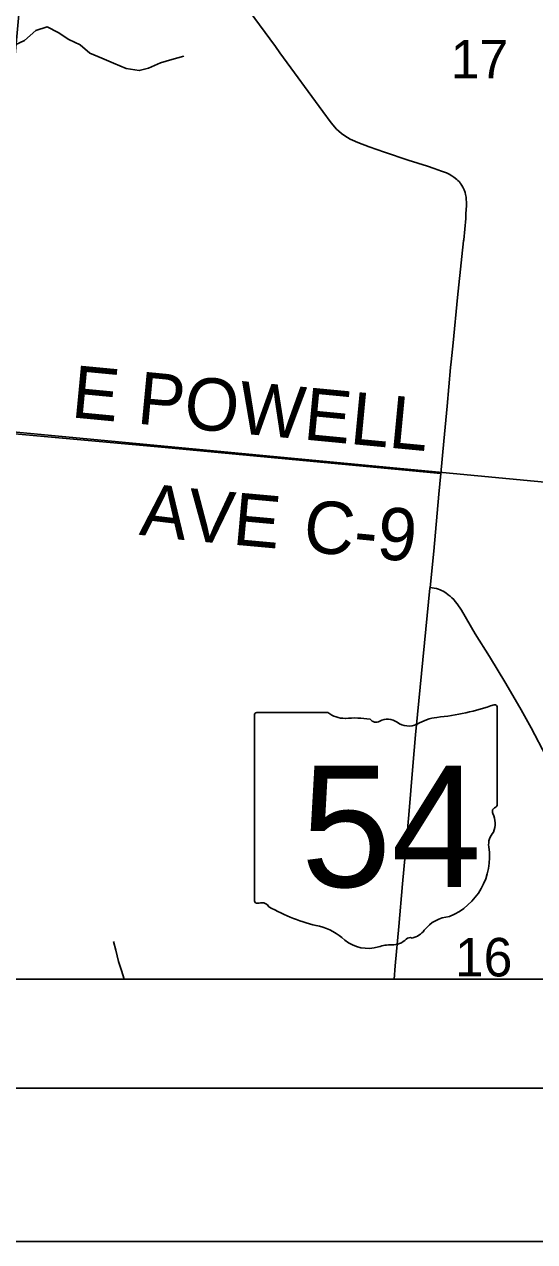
# Model space of a CAD drawing. Extents: x 0 to 1067, y 0 to 440.
# Drawn here: x 407.4 to 440.7, y 0 to 79.3 of the extents above; entities that cross this region are included whole.
import ezdxf

# ---------------------------------------------------------------- set-up
doc = ezdxf.new("R2010")
doc.units = 0
for name, color, linetype in [('GM_X_County_Road', 7, 'Continuous'), ('GM_X_County_Road_Text', 7, 'Continuous'), ('GM_X_Minor_River', 7, 'Continuous'), ('GM_X_Section', 7, 'Continuous'), ('GM_X_Section_Text', 7, 'Continuous'), ('GM_X_State_Location', 7, 'Continuous'), ('GM_X_State_Route', 7, 'Continuous'), ('GM_X_State_Shield', 7, 'Continuous'), ('GM_X_Township_Road', 7, 'Continuous'), ('SH_Border', 7, 'Continuous'), ('SH_Cut_Line', 7, 'Continuous'), ('SH_Text', 7, 'Continuous')]:
    doc.layers.add(name, color=color, linetype=linetype)

msp = doc.modelspace()

# ---------------------------------------------------------------- linework, layer by layer
at = {"layer": 'GM_X_County_Road'}
for points in [[(434.558, 50.033), (416.36, 51.756), (404.864, 52.807)], [(433.852, 42.626), (434.091, 44.99), (434.436, 48.691), (434.558, 50.033)], [(441.42, 31.603), (440.434, 33.484), (439.785, 34.657), (438.785, 36.36), (437.721, 38.112), (436.802, 39.605), (435.894, 41.147), (435.626, 41.545), (435.495, 41.711), (435.393, 41.828), (435.281, 41.944), (435.156, 42.054), (435.04, 42.146), (434.876, 42.267), (434.712, 42.368), (434.607, 42.423), (434.508, 42.47), (434.396, 42.513), (434.283, 42.545), (434.113, 42.581), (433.852, 42.626)]]:
    msp.add_lwpolyline(points, dxfattribs=at)
at = {"layer": 'GM_X_Minor_River'}
for points in [[(406.778, 77.948), (407.439, 78.262), (408.17, 78.893), (408.899, 79.137), (409.622, 78.768), (410.322, 78.307), (411.068, 77.96), (411.699, 77.432), (412.468, 77.107), (413.238, 76.783), (414.052, 76.435), (414.913, 76.292), (415.505, 76.446), (416.302, 76.804), (417.03, 77.003), (417.804, 77.224)], [(413.922, 17.107), (413.748, 17.67), (413.548, 18.241), (413.373, 18.993), (413.241, 19.563)]]:
    msp.add_lwpolyline(points, dxfattribs=at)
at = {"layer": 'GM_X_Section'}
msp.add_lwpolyline([(410.18, 114.397), (470.491, 107.701), (464.499, 47.289), (404.583, 52.958)], close=True, dxfattribs=at)
at = {"layer": 'GM_X_State_Route'}
msp.add_line((433.846, 42.567), (433.852, 42.626), dxfattribs=at)
for points in [[(435.793, 68.999), (435.762, 69.039), (435.663, 69.138), (435.599, 69.197), (435.405, 69.356), (435.277, 69.445), (435.103, 69.543), (434.92, 69.621), (434.606, 69.747), (434.13, 69.914), (433.696, 70.066), (432.431, 70.463), (430.878, 70.981), (429.88, 71.331), (429.156, 71.611), (428.803, 71.76), (428.646, 71.833), (428.474, 71.93), (428.296, 72.047), (428.087, 72.188), (427.909, 72.335), (427.768, 72.476), (427.412, 72.894), (426.863, 73.626), (424.068, 77.453), (423.792, 77.851), (421.397, 81.115)], [(436.047, 65.268), (436.176, 66.645), (436.195, 66.989), (436.22, 67.491), (436.22, 67.73), (436.215, 67.889), (436.197, 68.055), (436.17, 68.212), (436.135, 68.347), (436.071, 68.526), (435.988, 68.694), (435.924, 68.806), (435.852, 68.923), (435.824, 68.959), (435.793, 68.999)], [(435.227, 57.311), (435.361, 58.553), (435.647, 61.519), (435.917, 64.188), (436.042, 65.208), (436.047, 65.268)], [(434.558, 50.033), (434.753, 52.157), (434.964, 54.423), (435.193, 56.949), (435.227, 57.311)], [(433.852, 42.626), (434.091, 44.99), (434.436, 48.691), (434.558, 50.033)], [(431.52, 17.107), (431.591, 17.971), (431.813, 20.534), (432.051, 23.32), (432.317, 26.104), (432.466, 27.813), (432.731, 30.971), (432.916, 33.013), (433.036, 34.349), (433.846, 42.567)]]:
    msp.add_lwpolyline(points, dxfattribs=at)
at = {"layer": 'GM_X_State_Shield'}
for p, q in [((422.408, 34.269), (422.408, 22.261)), ((427.197, 34.475), (422.564, 34.475)), ((438.228, 28.492), (438.228, 34.773)), ((438.227, 28.493), (438.228, 28.492))]:
    msp.add_line(p, q, dxfattribs=at)
for centre, radius, start, end in [((432.593, 50.845), 16.777, 275.84447, 288.90645), ((438.053, 34.799), 0.176, 351.86209, 97.738), ((422.59, 34.294), 0.183, 98.1301, 188.1301), ((428.3, 35.869), 1.778, 231.61951, 271.11188), ((428.89, 27.734), 6.382, 80.48669, 94.98827), ((434.733, 30.808), 3.375, 97.34618, 120.76885), ((430.339, 34.356), 0.513, 219.79206, 297.10237), ((431.091, 32.969), 1.066, 54.46668, 119.14113), ((432.468, 34.872), 1.283, 233.85621, 294.82819), ((438.188, 28.03), 0.273, 107.94398, 210.33697), ((436.454, 27.237), 1.636, 340.03296, 23.64957), ((438.04, 28.467), 0.188, 289.60381, 7.73413), ((438.859, 25.863), 1.19, 136.8065, 186.92959), ((433.533, 25.064), 4.196, 292.30889, 8.98584), ((422.591, 22.235), 0.185, 171.95839, 258.30661), ((422.619, 23.464), 1.411, 267.33899, 280.60386), ((422.908, 21.569), 0.509, 29.74838, 93.27175), ((429.332, 32.357), 12.115, 240.41292, 257.1985), ((435.302, 18.89), 2.298, 94.40312, 142.57675), ((425.72, 16.867), 3.791, 47.18416, 75.83597), ((432.39, 21.098), 1.356, 282.87319, 323.27711), ((429.819, 21.509), 2.405, 230.70037, 286.29184), ((431.209, 17.358), 1.976, 85.69512, 111.20995), ((431.385, 20.61), 1.282, 268.77702, 315.54927), ((432.544, 19.447), 0.361, 65.75173, 132.64842)]:
    msp.add_arc(centre, radius, start, end, dxfattribs=at)
at = {"layer": 'GM_X_Township_Road'}
msp.add_lwpolyline([(216.022, 17.107), (539, 17.107)], dxfattribs=at)
at = {"layer": 'SH_Border'}
msp.add_lwpolyline([(30, 430), (670, 430), (670, 10), (30, 10)], close=True, dxfattribs=at)
at = {"layer": 'SH_Cut_Line'}
msp.add_lwpolyline([(0, 0), (680, 0), (680, 440), (0, 440)], close=True, dxfattribs=at)
at = {"layer": 'SH_Text'}
msp.add_lwpolyline([(131, 425.107), (539, 425.107), (539, 17.107), (131, 17.107)], close=True, dxfattribs=at)

# ---------------------------------------------------------------- texts
at = {"layer": 'GM_X_County_Road_Text'}
for s, height, rotation, p in [('E POWELL', 3.4091, 354.55351, (410.413, 53.708)), ('A', 3.409, 353.23058, (414.855, 46.056)), ('V', 3.409, 354.77216, (417.934, 45.692)), ('E', 3.409, 354.85543, (420.927, 45.418)), ('C-9', 3.4091, 354.47201, (425.508, 44.977))]:
    msp.add_text(s, height=height, rotation=rotation, dxfattribs=at).set_placement(p)
at = {"layer": 'GM_X_Section_Text'}
for s, p in [('17', (435.204, 75.783)), ('16', (435.479, 17.277))]:
    msp.add_text(s, height=2.5114, rotation=0.00001, dxfattribs=at).set_placement(p)
at = {"layer": 'GM_X_State_Location'}
for s in ['s', 'r']:
    msp.add_text(s, height=0.0114, dxfattribs=at).set_placement((430.14, 27.467))
msp.add_text('54', height=0.0114, rotation=0.00001, dxfattribs=at).set_placement((427.279, 26.64))
at = {"layer": 'GM_X_State_Shield'}
msp.add_text('54', height=7.9102, dxfattribs=at).set_placement((425.443, 23.108))

doc.saveas('drawing.dxf')
